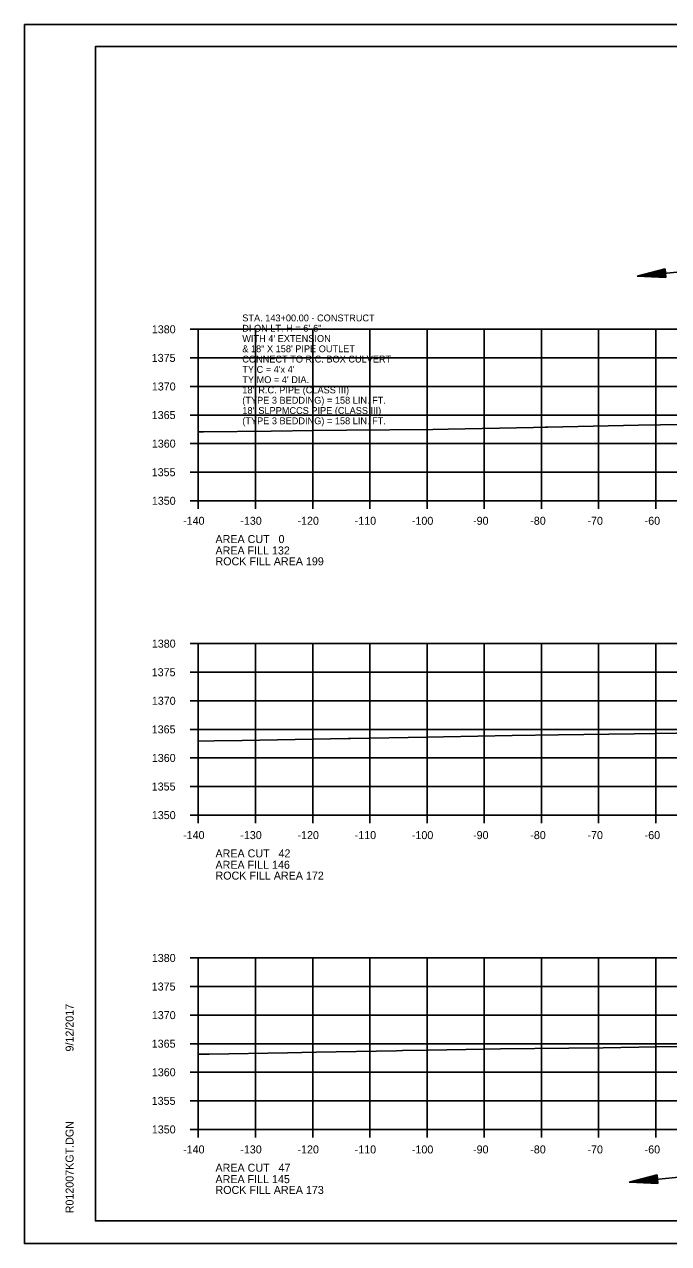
# Model space of a CAD drawing. Extents: x 1374311 to 1383814, y 384102 to 406278.
# Drawn here: x 1381458.2 to 1381570.9, y 389658 to 389871.4 of the extents above; entities that cross this region are included whole.
import ezdxf

# ---------------------------------------------------------------- set-up
doc = ezdxf.new("R2010")
doc.units = 0
for name, color, linetype in [('R_Axis', 7, 'Continuous'), ('R_Axis Annot', 7, 'Continuous'), ('R_Border', 7, 'Continuous'), ('R_Draft', 7, 'Continuous'), ('R_Exist Surface', 7, 'Continuous'), ('R_Grid', 7, 'Continuous'), ('R_No Plot', 7, 'Continuous'), ('R_Water', 7, 'Continuous'), ('R_Water Annot', 7, 'Continuous')]:
    doc.layers.add(name, color=color, linetype=linetype)

msp = doc.modelspace()

# ---------------------------------------------------------------- linework, layer by layer
at = {"layer": 'R_Axis'}
for p, q in [((1381487.26, 389818.03), (1381488.66, 389818.03)), ((1381488.66, 389788.03), (1381488.66, 389818.03)), ((1381487.26, 389813.03), (1381488.66, 389813.03)), ((1381487.26, 389808.03), (1381488.66, 389808.03)), ((1381487.26, 389803.03), (1381488.66, 389803.03)), ((1381487.26, 389798.03), (1381488.66, 389798.03)), ((1381487.26, 389793.03), (1381488.66, 389793.03)), ((1381487.26, 389788.03), (1381488.66, 389788.03)), ((1381488.66, 389788.03), (1381768.66, 389788.03)), ((1381488.66, 389786.63), (1381488.66, 389788.03)), ((1381498.66, 389786.63), (1381498.66, 389788.03)), ((1381508.66, 389786.63), (1381508.66, 389788.03)), ((1381518.66, 389786.63), (1381518.66, 389788.03)), ((1381528.66, 389786.63), (1381528.66, 389788.03)), ((1381538.66, 389786.63), (1381538.66, 389788.03)), ((1381548.66, 389786.63), (1381548.66, 389788.03)), ((1381558.66, 389786.63), (1381558.66, 389788.03)), ((1381568.66, 389786.63), (1381568.66, 389788.03)), ((1381487.26, 389763.03), (1381488.66, 389763.03)), ((1381488.66, 389733.03), (1381488.66, 389763.03)), ((1381487.26, 389758.03), (1381488.66, 389758.03)), ((1381487.26, 389753.03), (1381488.66, 389753.03)), ((1381487.26, 389748.03), (1381488.66, 389748.03)), ((1381487.26, 389743.03), (1381488.66, 389743.03)), ((1381487.26, 389738.03), (1381488.66, 389738.03)), ((1381487.26, 389733.03), (1381488.66, 389733.03)), ((1381488.66, 389733.03), (1381768.66, 389733.03)), ((1381488.66, 389731.63), (1381488.66, 389733.03)), ((1381498.66, 389731.63), (1381498.66, 389733.03)), ((1381508.66, 389731.63), (1381508.66, 389733.03)), ((1381518.66, 389731.63), (1381518.66, 389733.03)), ((1381528.66, 389731.63), (1381528.66, 389733.03)), ((1381538.66, 389731.63), (1381538.66, 389733.03)), ((1381548.66, 389731.63), (1381548.66, 389733.03)), ((1381558.66, 389731.63), (1381558.66, 389733.03)), ((1381568.66, 389731.63), (1381568.66, 389733.03)), ((1381487.26, 389708.03), (1381488.66, 389708.03)), ((1381488.66, 389678.03), (1381488.66, 389708.03)), ((1381487.26, 389703.03), (1381488.66, 389703.03)), ((1381487.26, 389698.03), (1381488.66, 389698.03)), ((1381487.26, 389693.03), (1381488.66, 389693.03)), ((1381487.26, 389688.03), (1381488.66, 389688.03)), ((1381487.26, 389683.03), (1381488.66, 389683.03)), ((1381487.26, 389678.03), (1381488.66, 389678.03)), ((1381488.66, 389678.03), (1381768.66, 389678.03)), ((1381488.66, 389676.63), (1381488.66, 389678.03)), ((1381498.66, 389676.63), (1381498.66, 389678.03)), ((1381508.66, 389676.63), (1381508.66, 389678.03)), ((1381518.66, 389676.63), (1381518.66, 389678.03)), ((1381528.66, 389676.63), (1381528.66, 389678.03)), ((1381538.66, 389676.63), (1381538.66, 389678.03)), ((1381548.66, 389676.63), (1381548.66, 389678.03)), ((1381558.66, 389676.63), (1381558.66, 389678.03)), ((1381568.66, 389676.63), (1381568.66, 389678.03))]:
    msp.add_line(p, q, dxfattribs=at)
at = {"layer": 'R_Border'}
for p, q in [((1381470.66, 389867.49), (1381786.84, 389867.49)), ((1381470.66, 389662.03), (1381470.66, 389867.49)), ((1381470.66, 389662.03), (1381470.66, 389662.03)), ((1381786.84, 389662.03), (1381470.66, 389662.03))]:
    msp.add_line(p, q, dxfattribs=at)
at = {"layer": 'R_Draft'}
for p, q in [((1381570.29, 389828.6), (1381565.39, 389827.36)), ((1381570.3, 389828.48), (1381566.22, 389827.44)), ((1381570.31, 389828.35), (1381567.07, 389827.53)), ((1381570.32, 389828.23), (1381567.9, 389827.61)), ((1381570.4, 389827.48), (1381567.9, 389827.61)), ((1381570.34, 389828.1), (1381568.74, 389827.69)), ((1381570.38, 389827.61), (1381568.74, 389827.69)), ((1381570.35, 389827.97), (1381569.57, 389827.78)), ((1381570.37, 389827.74), (1381569.57, 389827.78)), ((1381570.29, 389828.6), (1381570.43, 389827.11)), ((1381570.43, 389827.11), (1381565.39, 389827.36)), ((1381570.42, 389827.23), (1381566.22, 389827.44)), ((1381570.41, 389827.36), (1381567.07, 389827.53)), ((1381568.87, 389670.07), (1381563.97, 389668.83)), ((1381568.88, 389669.95), (1381564.8, 389668.92)), ((1381568.9, 389669.82), (1381565.66, 389669)), ((1381568.91, 389669.7), (1381566.48, 389669.08)), ((1381568.87, 389670.07), (1381569.02, 389668.58)), ((1381569.02, 389668.58), (1381563.97, 389668.83)), ((1381569.01, 389668.71), (1381564.8, 389668.92)), ((1381568.99, 389668.83), (1381565.66, 389669)), ((1381568.98, 389668.96), (1381566.48, 389669.08)), ((1381568.92, 389669.57), (1381567.33, 389669.17)), ((1381568.97, 389669.08), (1381567.33, 389669.17)), ((1381568.93, 389669.44), (1381568.16, 389669.25)), ((1381568.96, 389669.21), (1381568.16, 389669.25))]:
    msp.add_line(p, q, dxfattribs=at)
at = {"layer": 'R_Exist Surface'}
for points in [[(1381488.66, 389800.11), (1381489.57, 389800.12), (1381501.4, 389800.22), (1381508.81, 389800.3), (1381514.58, 389800.41), (1381529.68, 389800.5), (1381532.35, 389800.55), (1381547.26, 389800.87), (1381549.32, 389800.92), (1381549.76, 389800.93), (1381565.63, 389801.28), (1381569.49, 389801.34), (1381575.34, 389801.43)], [(1381488.66, 389745.97), (1381491.41, 389746.01), (1381496.3, 389746.08), (1381514.87, 389746.41), (1381514.95, 389746.41), (1381515.29, 389746.42), (1381528.71, 389746.67), (1381531.52, 389746.73), (1381543.53, 389746.97), (1381551.64, 389747.09), (1381564.89, 389747.23), (1381579.69, 389747.49)], [(1381488.66, 389691.17), (1381490.54, 389691.2), (1381504.28, 389691.44), (1381509.26, 389691.54), (1381523.32, 389691.8), (1381524.37, 389691.82), (1381528.87, 389691.9), (1381538.67, 389692.09), (1381541.48, 389692.14), (1381559.47, 389692.32), (1381568.76, 389692.48), (1381581.6, 389692.64)]]:
    msp.add_lwpolyline(points, dxfattribs=at)
at = {"layer": 'R_Grid'}
for p, q in [((1381488.66, 389818.03), (1381768.66, 389818.03)), ((1381488.66, 389788.03), (1381488.66, 389818.03)), ((1381498.66, 389788.03), (1381498.66, 389818.03)), ((1381508.66, 389788.03), (1381508.66, 389818.03)), ((1381518.66, 389788.03), (1381518.66, 389818.03)), ((1381528.66, 389788.03), (1381528.66, 389818.03)), ((1381538.66, 389788.03), (1381538.66, 389818.03)), ((1381548.66, 389788.03), (1381548.66, 389818.03)), ((1381558.66, 389788.03), (1381558.66, 389818.03)), ((1381568.66, 389788.03), (1381568.66, 389818.03)), ((1381488.66, 389813.03), (1381768.66, 389813.03)), ((1381488.66, 389808.03), (1381768.66, 389808.03)), ((1381488.66, 389803.03), (1381768.66, 389803.03)), ((1381488.66, 389798.03), (1381768.66, 389798.03)), ((1381488.66, 389793.03), (1381768.66, 389793.03)), ((1381488.66, 389788.03), (1381768.66, 389788.03)), ((1381488.66, 389763.03), (1381768.66, 389763.03)), ((1381488.66, 389733.03), (1381488.66, 389763.03)), ((1381498.66, 389733.03), (1381498.66, 389763.03)), ((1381508.66, 389733.03), (1381508.66, 389763.03)), ((1381518.66, 389733.03), (1381518.66, 389763.03)), ((1381528.66, 389733.03), (1381528.66, 389763.03)), ((1381538.66, 389733.03), (1381538.66, 389763.03)), ((1381548.66, 389733.03), (1381548.66, 389763.03)), ((1381558.66, 389733.03), (1381558.66, 389763.03)), ((1381568.66, 389733.03), (1381568.66, 389763.03)), ((1381488.66, 389758.03), (1381768.66, 389758.03)), ((1381488.66, 389753.03), (1381768.66, 389753.03)), ((1381488.66, 389748.03), (1381768.66, 389748.03)), ((1381488.66, 389743.03), (1381768.66, 389743.03)), ((1381488.66, 389738.03), (1381768.66, 389738.03)), ((1381488.66, 389733.03), (1381768.66, 389733.03)), ((1381488.66, 389708.03), (1381768.66, 389708.03)), ((1381488.66, 389678.03), (1381488.66, 389708.03)), ((1381498.66, 389678.03), (1381498.66, 389708.03)), ((1381508.66, 389678.03), (1381508.66, 389708.03)), ((1381518.66, 389678.03), (1381518.66, 389708.03)), ((1381528.66, 389678.03), (1381528.66, 389708.03)), ((1381538.66, 389678.03), (1381538.66, 389708.03)), ((1381548.66, 389678.03), (1381548.66, 389708.03)), ((1381558.66, 389678.03), (1381558.66, 389708.03)), ((1381568.66, 389678.03), (1381568.66, 389708.03)), ((1381488.66, 389703.03), (1381768.66, 389703.03)), ((1381488.66, 389698.03), (1381768.66, 389698.03)), ((1381488.66, 389693.03), (1381768.66, 389693.03)), ((1381488.66, 389688.03), (1381768.66, 389688.03)), ((1381488.66, 389683.03), (1381768.66, 389683.03)), ((1381488.66, 389678.03), (1381768.66, 389678.03))]:
    msp.add_line(p, q, dxfattribs=at)
at = {"layer": 'R_No Plot'}
for p, q in [((1381458.26, 389871.39), (1381791.59, 389871.39)), ((1381458.26, 389658.05), (1381791.59, 389658.05))]:
    msp.add_line(p, q, dxfattribs=at)
for points in [[(1381458.25, 389871.39), (1381791.59, 389871.39), (1381791.59, 389658.05), (1381458.25, 389658.05)], [(1381704.58, 389867.49), (1381704.58, 389857.61), (1381740.31, 389857.61), (1381740.31, 389854.69), (1381763.51, 389854.69), (1381763.51, 389831.48), (1381786.84, 389831.48), (1381786.84, 389662.03), (1381470.66, 389662.03), (1381470.66, 389867.49)]]:
    msp.add_lwpolyline(points, close=True, dxfattribs=at)
at = {"layer": 'R_Water'}
for p, q in [((1381575.84, 389828.4), (1381565.39, 389827.36)), ((1381574.42, 389669.87), (1381563.97, 389668.83))]:
    msp.add_line(p, q, dxfattribs=at)

# ---------------------------------------------------------------- texts
at = {"layer": 'R_Axis Annot'}
for s, p in [('1380', (1381480.53, 389817.33)), ('1375', (1381480.51, 389812.33)), ('1370', (1381480.53, 389807.33)), ('1365', (1381480.51, 389802.33)), ('1360', (1381480.53, 389797.33)), ('1355', (1381480.51, 389792.33)), ('1350', (1381480.53, 389787.33)), ('-140', (1381486, 389783.83)), ('-130', (1381496, 389783.83)), ('-120', (1381506, 389783.83)), ('-110', (1381516, 389783.83)), ('-100', (1381526, 389783.83)), ('-90', (1381536.7, 389783.83)), ('-80', (1381546.7, 389783.83)), ('-70', (1381556.7, 389783.83)), ('-60', (1381566.7, 389783.83)), ('AREA CUT   0', (1381491.66, 389780.63)), ('AREA FILL 132', (1381491.66, 389778.63)), ('ROCK FILL AREA 199', (1381491.66, 389776.74)), ('1380', (1381480.53, 389762.33)), ('1375', (1381480.51, 389757.33)), ('1370', (1381480.53, 389752.33)), ('1365', (1381480.51, 389747.33)), ('1360', (1381480.53, 389742.33)), ('1355', (1381480.51, 389737.33)), ('1350', (1381480.53, 389732.33)), ('-140', (1381486, 389728.83)), ('-130', (1381496, 389728.83)), ('-120', (1381506, 389728.83)), ('-110', (1381516, 389728.83)), ('-100', (1381526, 389728.83)), ('-90', (1381536.7, 389728.83)), ('-80', (1381546.7, 389728.83)), ('-70', (1381556.7, 389728.83)), ('-60', (1381566.7, 389728.83)), ('AREA CUT   42', (1381491.66, 389725.63)), ('AREA FILL 146', (1381491.66, 389723.63)), ('ROCK FILL AREA 172', (1381491.66, 389721.74)), ('1380', (1381480.53, 389707.33)), ('1375', (1381480.51, 389702.33)), ('1370', (1381480.53, 389697.33)), ('1365', (1381480.51, 389692.33)), ('1360', (1381480.53, 389687.33)), ('1355', (1381480.51, 389682.33)), ('1350', (1381480.53, 389677.33)), ('-140', (1381486, 389673.83)), ('-130', (1381496, 389673.83)), ('-120', (1381506, 389673.83)), ('-110', (1381516, 389673.83)), ('-100', (1381526, 389673.83)), ('-90', (1381536.7, 389673.83)), ('-80', (1381546.7, 389673.83)), ('-70', (1381556.7, 389673.83)), ('-60', (1381566.7, 389673.83)), ('AREA CUT   47', (1381491.66, 389670.63)), ('AREA FILL 145', (1381491.66, 389668.63)), ('ROCK FILL AREA 173', (1381491.66, 389666.74))]:
    msp.add_text(s, height=1.4, dxfattribs=at).set_placement(p)
at = {"layer": 'R_Border'}
for s, p in [('9/12/2017', (1381466.85, 389691.67)), ('R012007KGT.DGN', (1381466.85, 389663.36))]:
    msp.add_text(s, height=1.4, rotation=90, dxfattribs=at).set_placement(p)
at = {"layer": 'R_Water Annot'}
for s, p in [('STA. 143+00.00 - CONSTRUCT', (1381496.35, 389819.42)), ("WITH 4' EXTENSION ", (1381496.35, 389815.82)), ('DI ON LT. H = 6\'-6"', (1381496.35, 389817.62)), ('& 18" X 158\' PIPE OUTLET', (1381496.35, 389814.02)), ('CONNECT TO R.C. BOX CULVERT', (1381496.35, 389812.22)), ("TY C = 4'x 4'", (1381496.35, 389810.42)), ("TY MO = 4' DIA.", (1381496.35, 389808.62)), ('(TYPE 3 BEDDING) = 158 LIN. FT.', (1381496.35, 389805.02)), ('18" R.C. PIPE (CLASS III)', (1381496.35, 389806.82)), ('18" SLPPMCCS PIPE (CLASS III)', (1381496.35, 389803.22)), ('(TYPE 3 BEDDING) = 158 LIN. FT.', (1381496.35, 389801.42))]:
    msp.add_text(s, height=1.2, dxfattribs=at).set_placement(p)

doc.saveas('drawing.dxf')
